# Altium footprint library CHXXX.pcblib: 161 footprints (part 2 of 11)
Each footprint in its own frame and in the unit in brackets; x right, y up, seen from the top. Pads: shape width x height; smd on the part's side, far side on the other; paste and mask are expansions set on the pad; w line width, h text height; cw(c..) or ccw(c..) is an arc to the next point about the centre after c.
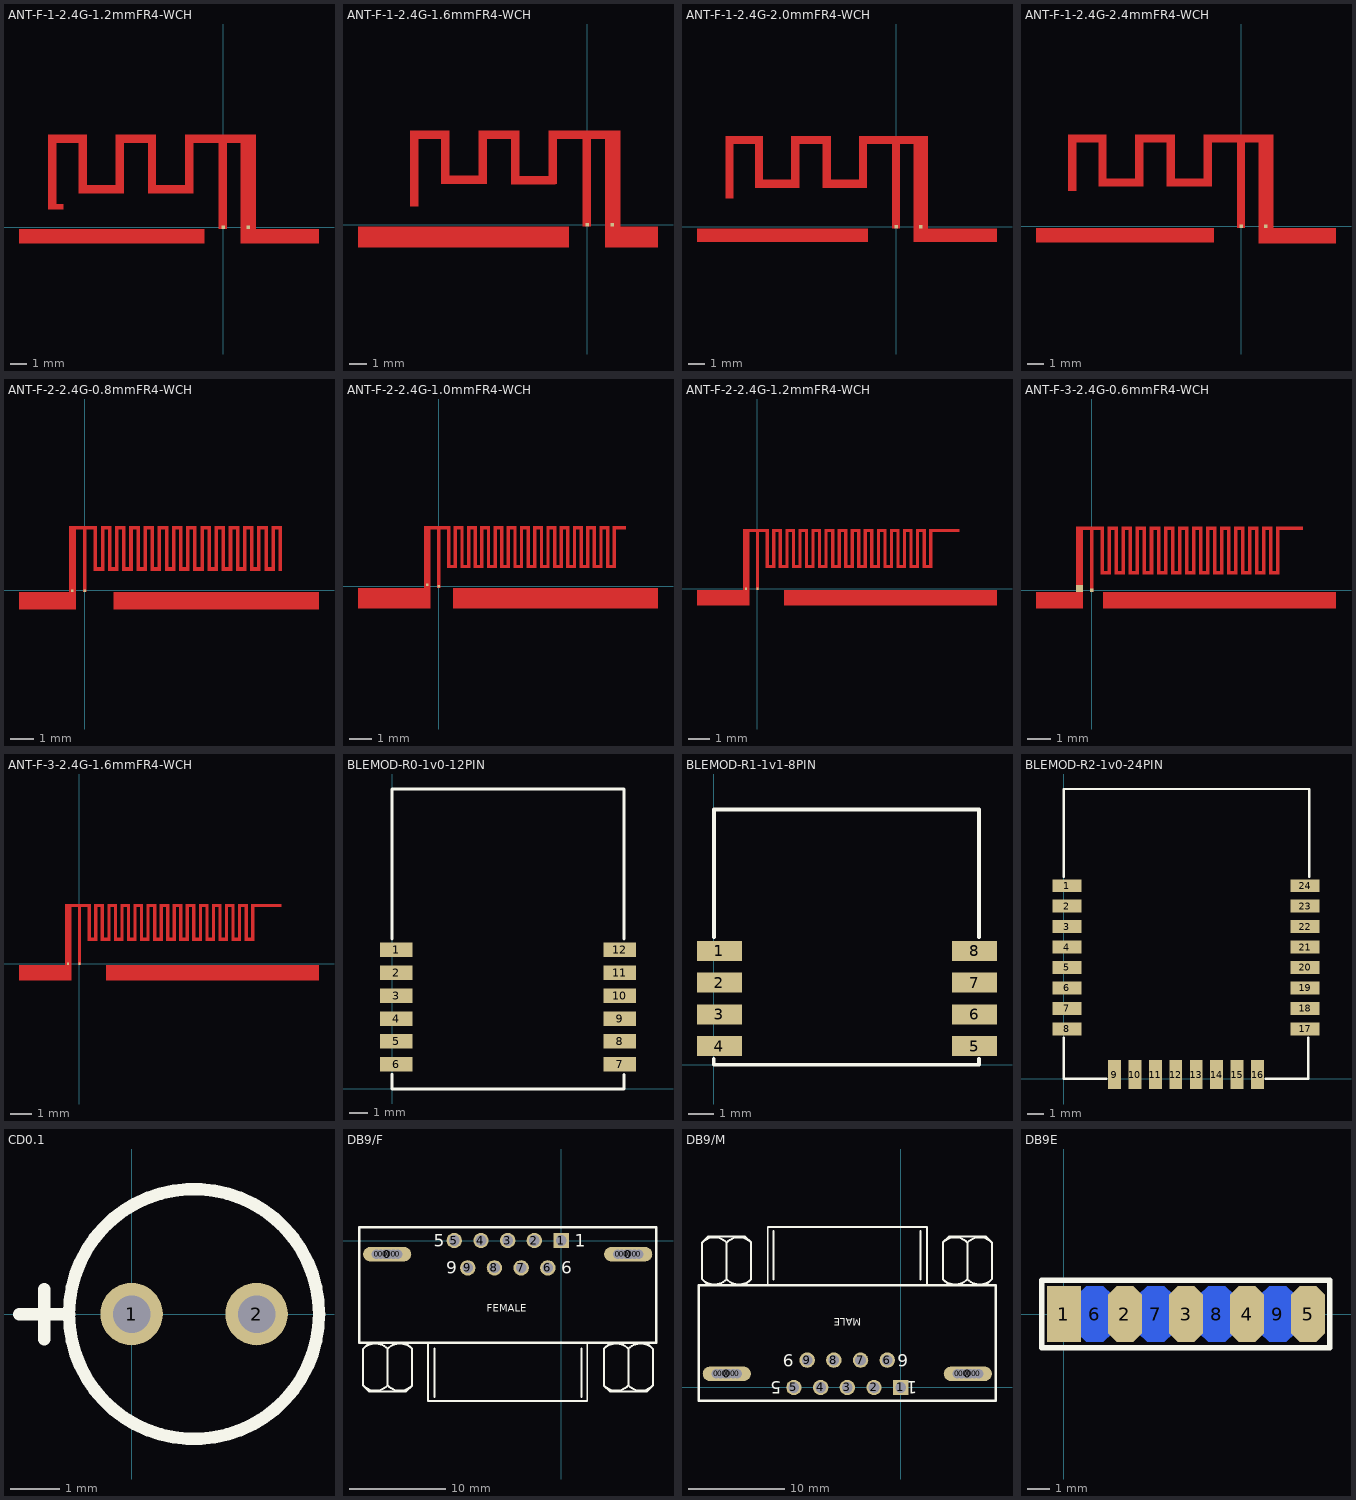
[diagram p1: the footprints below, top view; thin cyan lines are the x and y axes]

## ANT-F-1-2.4G-1.2mmFR4-WCH [mm]
pads (2):
  rect 0.2x0.2 smd mask+0: 0(1.483,0) 1(0,0)
TopLayer:
  region: -9.86,5.18 -10.36,5.18 -10.36,1.06 -9.86,1.06
  region: -8.06,5.5 -10.36,5.5 -10.36,5 -8.06,5
  region: -8.06,5.18 -8.56,5.18 -8.56,2 -8.06,2
  region: -5.875,2.5 -8.364,2.5 -8.364,2 -5.875,2
  region: -5.86,5.18 -6.36,5.18 -6.36,2 -5.86,2
  region: -3.96,5.5 -6.36,5.5 -6.36,5 -3.96,5
  region: -3.96,5.18 -4.46,5.18 -4.46,2 -3.96,2
  region: -1.85,2.5 -4.39,2.5 -4.39,2 -1.85,2
  region: -1.76,5.18 -2.26,5.18 -2.26,2 -1.76,2
  region: 1.94,5.5 -2.26,5.5 -2.26,5 1.94,5
  region: 1.94,5.205 1.04,5.205 1.04,-0.1 1.94,-0.1
  region: 0.24,5.231 -0.26,5.231 -0.26,-0.1 0.24,-0.1
  region: -9.46,1.36 -10.36,1.36 -10.36,1.06 -9.46,1.06
  rectangle: -12.086,-0.978 -1.093,-0.1
  rectangle: 1.04,-0.978 5.679,-0.1
Mechanical13:
  text "适用FR4板材，1.2mm板厚，封装未开窗，建议天线开窗。技术咨询 tech@wch.cn" at -10.498,-4.902 h0.4
  text "GND" at -9.371,-1.808 h0.89
  text "GND" at 0.936,-1.808 h0.89

## ANT-F-1-2.4G-1.6mmFR4-WCH [mm]
pads (2):
  rect 0.2x0.2 smd mask+0: 0(1.483,0) 1(0,0)
TopLayer:
  region: 0.24,5.231 -0.26,5.231 -0.26,-0.1 0.24,-0.1
  region: 1.94,5.206 1.04,5.206 1.04,-0.1 1.94,-0.1
  region: 1.94,5.5 -2.26,5.5 -2.26,5 1.94,5
  region: -1.76,5.181 -2.26,5.181 -2.26,2.361 -1.76,2.361
  region: -1.85,2.855 -4.39,2.855 -4.39,2.36 -1.85,2.36
  region: -3.96,5.18 -4.46,5.18 -4.46,2.36 -3.96,2.36
  region: -3.96,5.5 -6.36,5.5 -6.36,5 -3.96,5
  region: -5.86,5.181 -6.36,5.181 -6.36,2.361 -5.86,2.361
  region: -5.875,2.861 -8.364,2.861 -8.364,2.361 -5.875,2.361
  region: -8.06,5.181 -8.56,5.181 -8.56,2.361 -8.06,2.361
  region: -8.06,5.5 -10.36,5.5 -10.36,5 -8.06,5
  region: -9.86,5.18 -10.36,5.18 -10.36,1.06 -9.86,1.06
  rectangle: 1.04,-1.335 4.149,-0.1
  rectangle: -13.408,-1.335 -1.064,-0.1
Mechanical13:
  text "GND" at -9.082,-1.74 h0.89
  text "GND" at 1.225,-1.74 h0.89
  text "适用FR4板材，1.6mm板厚，封装未开窗，建议天线开窗。技术咨询 tech@wch.cn" at -10.511,-5.125 h0.4

## ANT-F-1-2.4G-2.0mmFR4-WCH [mm]
pads (2):
  rect 0.2x0.2 smd mask+0: 0(1.483,0) 1(0,0)
TopLayer:
  rectangle: 1.04,-0.928 6.113,-0.1
  rectangle: -12.073,-0.928 -1.72,-0.1
  region: 0.24,5.231 -0.26,5.231 -0.26,-0.1 0.24,-0.1
  region: 1.94,5.206 1.04,5.206 1.04,-0.1 1.94,-0.1
  region: 1.94,5.5 -2.26,5.5 -2.26,5 1.94,5
  region: -1.76,5.181 -2.26,5.181 -2.26,2.361 -1.76,2.361
  region: -1.85,2.855 -4.39,2.855 -4.39,2.36 -1.85,2.36
  region: -3.96,5.18 -4.46,5.18 -4.46,2.36 -3.96,2.36
  region: -3.96,5.5 -6.36,5.5 -6.36,5 -3.96,5
  region: -5.86,5.181 -6.36,5.181 -6.36,2.361 -5.86,2.361
  region: -5.875,2.861 -8.364,2.861 -8.364,2.361 -5.875,2.361
  region: -8.06,5.181 -8.56,5.181 -8.56,2.361 -8.06,2.361
  region: -8.06,5.5 -10.36,5.5 -10.36,5 -8.06,5
  region: -9.86,5.18 -10.36,5.18 -10.36,1.7 -9.86,1.7
Mechanical13:
  text "适用FR4板材，2.0mm板厚，封装未开窗，建议天线开窗。技术咨询 tech@wch.cn" at -10.433,-4.732 h0.4
  text "GND" at 1.5,-1.841 h0.89
  text "GND" at -8.807,-1.841 h0.89

## ANT-F-1-2.4G-2.4mmFR4-WCH [mm]
pads (2):
  rect 0.2x0.2 smd mask+0: 0(1.483,0) 1(0,0)
TopLayer:
  rectangle: 1.04,-1.05 5.683,-0.1
  rectangle: -12.291,-0.983 -1.62,-0.1
  region: 0.24,5.231 -0.26,5.231 -0.26,-0.1 0.24,-0.1
  region: 1.94,5.206 1.04,5.206 1.04,-0.1 1.94,-0.1
  region: 1.94,5.5 -2.26,5.5 -2.26,5 1.94,5
  region: -1.76,5.181 -2.26,5.181 -2.26,2.361 -1.76,2.361
  region: -1.85,2.855 -4.39,2.855 -4.39,2.36 -1.85,2.36
  region: -3.96,5.18 -4.46,5.18 -4.46,2.36 -3.96,2.36
  region: -3.96,5.5 -6.36,5.5 -6.36,5 -3.96,5
  region: -5.86,5.181 -6.36,5.181 -6.36,2.361 -5.86,2.361
  region: -5.875,2.861 -8.364,2.861 -8.364,2.361 -5.875,2.361
  region: -8.06,5.181 -8.56,5.181 -8.56,2.361 -8.06,2.361
  region: -8.06,5.5 -10.36,5.5 -10.36,5 -8.06,5
  region: -9.86,5.18 -10.36,5.18 -10.36,2.1 -9.86,2.1
Mechanical13:
  text "适用FR4板材，2.4mm板厚，封装未开窗，建议天线开窗。技术咨询 tech@wch.cn" at -10.269,-5.379 h0.4
  text "GND" at -8.263,-1.666 h0.89
  text "GND" at 2.044,-1.666 h0.89

## ANT-F-2-2.4G-0.8mmFR4-WCH [mm]
pads (2):
  rect 0.1x0.1 smd mask+0: 0(-0.525,-0.025) 1(0,-0.025)
TopLayer:
  rectangle: 7.875,0.825 8.025,2.725
  rectangle: 7.575,0.825 8.025,0.975
  rectangle: 6.675,0.825 6.825,2.725
  rectangle: 6.975,0.825 7.125,2.725
  rectangle: 7.275,0.825 7.425,2.725
  rectangle: 7.575,0.825 7.725,2.725
  rectangle: 6.675,2.575 7.125,2.725
  rectangle: 7.275,2.575 7.725,2.725
  rectangle: 6.375,0.825 6.825,0.975
  rectangle: 6.975,0.825 7.425,0.975
  rectangle: 5.475,0.825 5.625,2.725
  rectangle: 5.775,0.825 5.925,2.725
  rectangle: 6.075,0.825 6.225,2.725
  rectangle: 6.375,0.825 6.525,2.725
  rectangle: 5.475,2.575 5.925,2.725
  rectangle: 6.075,2.575 6.525,2.725
  rectangle: 5.175,0.825 5.625,0.975
  rectangle: 5.775,0.825 6.225,0.975
  rectangle: 4.275,0.825 4.425,2.725
  rectangle: 4.575,0.825 4.725,2.725
  rectangle: 4.875,0.825 5.025,2.725
  rectangle: 5.175,0.825 5.325,2.725
  rectangle: 4.275,2.575 4.725,2.725
  rectangle: 4.875,2.575 5.325,2.725
  rectangle: 3.975,0.825 4.425,0.975
  rectangle: 4.575,0.825 5.025,0.975
  rectangle: 3.075,0.825 3.225,2.725
  rectangle: 3.375,0.825 3.525,2.725
  rectangle: 3.675,0.825 3.825,2.725
  rectangle: 3.975,0.825 4.125,2.725
  rectangle: 3.075,2.575 3.525,2.725
  rectangle: 3.675,2.575 4.125,2.725
  rectangle: 2.775,0.825 3.225,0.975
  rectangle: 3.375,0.825 3.825,0.975
  rectangle: 1.875,0.825 2.025,2.725
  rectangle: 2.175,0.825 2.325,2.725
  rectangle: 2.475,0.825 2.625,2.725
  rectangle: 2.775,0.825 2.925,2.725
  rectangle: 1.875,2.575 2.325,2.725
  rectangle: 2.475,2.575 2.925,2.725
  rectangle: 1.575,0.825 2.025,0.975
  rectangle: 2.175,0.825 2.625,0.975
  rectangle: 0.975,0.825 1.425,0.975
  rectangle: 0.375,0.825 0.825,0.975
  rectangle: 1.275,2.575 1.725,2.725
  rectangle: 0.675,2.575 1.125,2.725
  rectangle: -0.075,2.575 0.525,2.725
  rectangle: 1.575,0.825 1.725,2.725
  rectangle: 1.275,0.825 1.425,2.725
  rectangle: 0.975,0.825 1.125,2.725
  rectangle: 0.675,0.825 0.825,2.725
  rectangle: 0.375,0.825 0.525,2.725
  region: 0.075,2.575 0.075,2.725 -0.675,2.725 -0.675,2.575
  rectangle: -0.075,-0.075 0.075,2.725
  rectangle: -0.675,-0.075 -0.375,2.725
  rectangle: 8.175,0.825 8.325,2.725
  rectangle: 7.875,2.575 8.325,2.725
  rectangle: 1.215,-0.802 9.885,-0.075
  rectangle: -2.777,-0.802 -0.375,-0.075
Mechanical13:
  text "GND" at -2.691,-1.393 h0.89
  text "GND" at 3.964,-1.393 h0.89
  text "适用FR4板材，0.8mm板厚，封装未开窗，建议天线开窗。技术咨询 tech@wch.cn" at -3.002,-4.172 h0.4

## ANT-F-2-2.4G-1.0mmFR4-WCH [mm]
pads (2):
  rect 0.1x0.1 smd mask+0: 0(-0.525,0.075) 1(0,0)
TopLayer:
  rectangle: 0.633,-1.001 9.934,-0.075
  rectangle: -3.664,-1.001 -0.375,-0.075
  rectangle: 7.875,2.575 8.475,2.725
  rectangle: 7.875,0.825 8.025,2.725
  rectangle: 7.575,0.825 8.025,0.975
  rectangle: 6.675,0.825 6.825,2.725
  rectangle: 6.975,0.825 7.125,2.725
  rectangle: 7.275,0.825 7.425,2.725
  rectangle: 7.575,0.825 7.725,2.725
  rectangle: 6.675,2.575 7.125,2.725
  rectangle: 7.275,2.575 7.725,2.725
  rectangle: 6.375,0.825 6.825,0.975
  rectangle: 6.975,0.825 7.425,0.975
  rectangle: 5.475,0.825 5.625,2.725
  rectangle: 5.775,0.825 5.925,2.725
  rectangle: 6.075,0.825 6.225,2.725
  rectangle: 6.375,0.825 6.525,2.725
  rectangle: 5.475,2.575 5.925,2.725
  rectangle: 6.075,2.575 6.525,2.725
  rectangle: 5.175,0.825 5.625,0.975
  rectangle: 5.775,0.825 6.225,0.975
  rectangle: 4.275,0.825 4.425,2.725
  rectangle: 4.575,0.825 4.725,2.725
  rectangle: 4.875,0.825 5.025,2.725
  rectangle: 5.175,0.825 5.325,2.725
  rectangle: 4.275,2.575 4.725,2.725
  rectangle: 4.875,2.575 5.325,2.725
  rectangle: 3.975,0.825 4.425,0.975
  rectangle: 4.575,0.825 5.025,0.975
  rectangle: 3.075,0.825 3.225,2.725
  rectangle: 3.375,0.825 3.525,2.725
  rectangle: 3.675,0.825 3.825,2.725
  rectangle: 3.975,0.825 4.125,2.725
  rectangle: 3.075,2.575 3.525,2.725
  rectangle: 3.675,2.575 4.125,2.725
  rectangle: 2.775,0.825 3.225,0.975
  rectangle: 3.375,0.825 3.825,0.975
  rectangle: 1.875,0.825 2.025,2.725
  rectangle: 2.175,0.825 2.325,2.725
  rectangle: 2.475,0.825 2.625,2.725
  rectangle: 2.775,0.825 2.925,2.725
  rectangle: 1.875,2.575 2.325,2.725
  rectangle: 2.475,2.575 2.925,2.725
  rectangle: 1.575,0.825 2.025,0.975
  rectangle: 2.175,0.825 2.625,0.975
  rectangle: 0.975,0.825 1.425,0.975
  rectangle: 0.375,0.825 0.825,0.975
  rectangle: 1.275,2.575 1.725,2.725
  rectangle: 0.675,2.575 1.125,2.725
  rectangle: 0.075,2.575 0.525,2.725
  rectangle: 1.575,0.825 1.725,2.725
  rectangle: 1.275,0.825 1.425,2.725
  rectangle: 0.975,0.825 1.125,2.725
  rectangle: 0.675,0.825 0.825,2.725
  rectangle: 0.375,0.825 0.525,2.725
  region: 0.075,2.575 0.075,2.725 -0.675,2.725 -0.675,2.575
  rectangle: -0.075,-0.075 0.075,2.725
  rectangle: -0.675,-0.075 -0.375,2.725
Mechanical13:
  text "适用FR4板材，1.0mm板厚，封装未开窗，建议天线开窗。技术咨询 tech@wch.cn" at -3.825,-2.709 h0.4
  text "GND" at -3.874,-1.213 h0.89
  text "GND" at 6.433,-1.213 h0.89

## ANT-F-2-2.4G-1.2mmFR4-WCH [mm]
pads (2):
  rect 0.1x0.1 smd mask+0: 0(-0.525,0) 1(0,0)
TopLayer:
  rectangle: -0.675,-0.05 -0.375,2.75
  rectangle: -0.075,-0.05 0.075,2.75
  region: 0.075,2.6 0.075,2.75 -0.675,2.75 -0.675,2.6
  rectangle: 0.375,0.95 0.525,2.75
  rectangle: 0.675,0.95 0.825,2.75
  rectangle: 0.975,0.95 1.125,2.75
  rectangle: 1.275,0.95 1.425,2.75
  rectangle: 1.575,0.95 1.725,2.75
  rectangle: 0.075,2.6 0.525,2.75
  rectangle: 0.675,2.6 1.125,2.75
  rectangle: 1.275,2.6 1.725,2.75
  rectangle: 0.375,0.95 0.825,1.1
  rectangle: 0.975,0.95 1.425,1.1
  rectangle: 2.175,0.95 2.625,1.1
  rectangle: 1.575,0.95 2.025,1.1
  rectangle: 2.475,2.6 2.925,2.75
  rectangle: 1.875,2.6 2.325,2.75
  rectangle: 2.775,0.95 2.925,2.75
  rectangle: 2.475,0.95 2.625,2.75
  rectangle: 2.175,0.95 2.325,2.75
  rectangle: 1.875,0.95 2.025,2.75
  rectangle: 3.375,0.95 3.825,1.1
  rectangle: 2.775,0.95 3.225,1.1
  rectangle: 3.675,2.6 4.125,2.75
  rectangle: 3.075,2.6 3.525,2.75
  rectangle: 3.975,0.95 4.125,2.75
  rectangle: 3.675,0.95 3.825,2.75
  rectangle: 3.375,0.95 3.525,2.75
  rectangle: 3.075,0.95 3.225,2.75
  rectangle: 4.575,0.95 5.025,1.1
  rectangle: 3.975,0.95 4.425,1.1
  rectangle: 4.875,2.6 5.325,2.75
  rectangle: 4.275,2.6 4.725,2.75
  rectangle: 5.175,0.95 5.325,2.75
  rectangle: 4.875,0.95 5.025,2.75
  rectangle: 4.575,0.95 4.725,2.75
  rectangle: 4.275,0.95 4.425,2.75
  rectangle: 5.775,0.95 6.225,1.1
  rectangle: 5.175,0.95 5.625,1.1
  rectangle: 6.075,2.6 6.525,2.75
  rectangle: 5.475,2.6 5.925,2.75
  rectangle: 6.375,0.95 6.525,2.75
  rectangle: 6.075,0.95 6.225,2.75
  rectangle: 5.775,0.95 5.925,2.75
  rectangle: 5.475,0.95 5.625,2.75
  rectangle: 6.975,0.95 7.425,1.1
  rectangle: 6.375,0.95 6.825,1.1
  rectangle: 7.275,2.6 7.725,2.75
  rectangle: 6.675,2.6 7.125,2.75
  rectangle: 7.575,0.95 7.725,2.75
  rectangle: 7.275,0.95 7.425,2.75
  rectangle: 6.975,0.95 7.125,2.75
  rectangle: 6.675,0.95 6.825,2.75
  rectangle: 7.575,0.95 8.025,1.1
  rectangle: 7.875,2.6 9.275,2.75
  rectangle: 7.875,0.95 8.025,2.75
  rectangle: 1.215,-0.777 10.994,-0.05
  rectangle: -2.777,-0.777 -0.375,-0.05
Mechanical13:
  text "适用FR4板材，1.2mm板厚，封装未开窗，建议天线开窗。技术咨询 tech@wch.cn" at -2.709,-3.856 h0.4
  text "GND" at -3.295,-1.368 h0.89
  text "GND" at 3.964,-1.368 h0.89

## ANT-F-3-2.4G-0.6mmFR4-WCH [mm]
pads (2):
  rect 0.3x0.3 smd mask+0: 0(-0.525,0.075)
  rect 0.15x0.15 smd mask+0: 1(0,0)
TopLayer:
  rectangle: -0.675,-0.075 -0.375,2.725
  rectangle: -0.075,-0.075 0.075,2.725
  region: 0.075,2.575 0.075,2.725 -0.675,2.725 -0.675,2.575
  rectangle: 0.375,0.675 0.525,2.725
  rectangle: 0.675,0.675 0.825,2.725
  rectangle: 0.975,0.675 1.125,2.725
  rectangle: 1.275,0.675 1.425,2.725
  rectangle: 1.575,0.675 1.725,2.725
  rectangle: 0.075,2.575 0.525,2.725
  rectangle: 0.675,2.575 1.125,2.725
  rectangle: 1.275,2.575 1.725,2.725
  rectangle: 0.375,0.675 0.825,0.825
  rectangle: 0.975,0.675 1.425,0.825
  rectangle: 2.175,0.675 2.625,0.825
  rectangle: 1.575,0.675 2.025,0.825
  rectangle: 2.475,2.575 2.925,2.725
  rectangle: 1.875,2.575 2.325,2.725
  rectangle: 2.775,0.675 2.925,2.725
  rectangle: 2.475,0.675 2.625,2.725
  rectangle: 2.175,0.675 2.325,2.725
  rectangle: 1.875,0.675 2.025,2.725
  rectangle: 3.375,0.675 3.825,0.825
  rectangle: 2.775,0.675 3.225,0.825
  rectangle: 3.675,2.575 4.125,2.725
  rectangle: 3.075,2.575 3.525,2.725
  rectangle: 3.975,0.675 4.125,2.725
  rectangle: 3.675,0.675 3.825,2.725
  rectangle: 3.375,0.675 3.525,2.725
  rectangle: 3.075,0.675 3.225,2.725
  rectangle: 4.575,0.675 5.025,0.825
  rectangle: 3.975,0.675 4.425,0.825
  rectangle: 4.875,2.575 5.325,2.725
  rectangle: 4.275,2.575 4.725,2.725
  rectangle: 5.175,0.675 5.325,2.725
  rectangle: 4.875,0.675 5.025,2.725
  rectangle: 4.575,0.675 4.725,2.725
  rectangle: 4.275,0.675 4.425,2.725
  rectangle: 5.775,0.675 6.225,0.825
  rectangle: 5.175,0.675 5.625,0.825
  rectangle: 6.075,2.575 6.525,2.725
  rectangle: 5.475,2.575 5.925,2.725
  rectangle: 6.375,0.675 6.525,2.725
  rectangle: 6.075,0.675 6.225,2.725
  rectangle: 5.775,0.675 5.925,2.725
  rectangle: 5.475,0.675 5.625,2.725
  rectangle: 6.975,0.675 7.425,0.825
  rectangle: 6.375,0.675 6.825,0.825
  rectangle: 7.275,2.575 7.725,2.725
  rectangle: 6.675,2.575 7.125,2.725
  rectangle: 7.575,0.675 7.725,2.725
  rectangle: 7.275,0.675 7.425,2.725
  rectangle: 6.975,0.675 7.125,2.725
  rectangle: 6.675,0.675 6.825,2.725
  rectangle: 7.575,0.675 8.025,0.825
  rectangle: 7.875,2.575 9.025,2.725
  rectangle: 7.875,0.675 8.025,2.725
  rectangle: 0.484,-0.765 10.438,-0.075
  rectangle: -2.388,-0.765 -0.375,-0.075
Mechanical13:
  text "GND" at 4.348,-1.194 h0.89
  text "GND" at -2.911,-1.194 h0.89
  text "适用FR4板材，0.6mm板厚，封装未开窗，建议天线开窗。技术咨询 tech@wch.cn" at -3.041,-2.982 h0.4

## ANT-F-3-2.4G-1.6mmFR4-WCH [mm]
pads (2):
  rect 0.1x0.1 smd mask+0: 0(-0.525,0) 1(0,0)
TopLayer:
  rectangle: 1.215,-0.777 10.994,-0.05
  rectangle: -2.777,-0.777 -0.375,-0.05
  rectangle: -0.675,-0.05 -0.375,2.75
  rectangle: -0.075,-0.05 0.075,2.75
  region: 0.075,2.6 0.075,2.75 -0.675,2.75 -0.675,2.6
  rectangle: 0.375,1.05 0.525,2.75
  rectangle: 0.675,1.05 0.825,2.75
  rectangle: 0.975,1.05 1.125,2.75
  rectangle: 1.275,1.05 1.425,2.75
  rectangle: 1.575,1.05 1.725,2.75
  rectangle: 0.075,2.6 0.525,2.75
  rectangle: 0.675,2.6 1.125,2.75
  rectangle: 1.275,2.6 1.725,2.75
  rectangle: 0.375,1.05 0.825,1.2
  rectangle: 0.975,1.05 1.425,1.2
  rectangle: 2.175,1.05 2.625,1.2
  rectangle: 1.575,1.05 2.025,1.2
  rectangle: 2.475,2.6 2.925,2.75
  rectangle: 1.875,2.6 2.325,2.75
  rectangle: 2.775,1.05 2.925,2.75
  rectangle: 2.475,1.05 2.625,2.75
  rectangle: 2.175,1.05 2.325,2.75
  rectangle: 1.875,1.05 2.025,2.75
  rectangle: 3.375,1.05 3.825,1.2
  rectangle: 2.775,1.05 3.225,1.2
  rectangle: 3.675,2.6 4.125,2.75
  rectangle: 3.075,2.6 3.525,2.75
  rectangle: 3.975,1.05 4.125,2.75
  rectangle: 3.675,1.05 3.825,2.75
  rectangle: 3.375,1.05 3.525,2.75
  rectangle: 3.075,1.05 3.225,2.75
  rectangle: 4.575,1.05 5.025,1.2
  rectangle: 3.975,1.05 4.425,1.2
  rectangle: 4.875,2.6 5.325,2.75
  rectangle: 4.275,2.6 4.725,2.75
  rectangle: 5.175,1.05 5.325,2.75
  rectangle: 4.875,1.05 5.025,2.75
  rectangle: 4.575,1.05 4.725,2.75
  rectangle: 4.275,1.05 4.425,2.75
  rectangle: 5.775,1.05 6.225,1.2
  rectangle: 5.175,1.05 5.625,1.2
  rectangle: 6.075,2.6 6.525,2.75
  rectangle: 5.475,2.6 5.925,2.75
  rectangle: 6.375,1.05 6.525,2.75
  rectangle: 6.075,1.05 6.225,2.75
  rectangle: 5.775,1.05 5.925,2.75
  rectangle: 5.475,1.05 5.625,2.75
  rectangle: 6.975,1.05 7.425,1.2
  rectangle: 6.375,1.05 6.825,1.2
  rectangle: 7.275,2.6 7.725,2.75
  rectangle: 6.675,2.6 7.125,2.75
  rectangle: 7.575,1.05 7.725,2.75
  rectangle: 7.275,1.05 7.425,2.75
  rectangle: 6.975,1.05 7.125,2.75
  rectangle: 6.675,1.05 6.825,2.75
  rectangle: 7.575,1.05 8.025,1.2
  rectangle: 7.875,2.6 9.275,2.75
  rectangle: 7.875,1.05 8.025,2.75
Mechanical13:
  text "GND" at 3.964,-1.368 h0.89
  text "GND" at -2.792,-1.368 h0.89
  text "适用FR4板材，1.6mm板厚，封装未开窗，建议天线开窗。技术咨询 tech@wch.cn" at -2.758,-4.352 h0.4

## BLEMOD-R0-1v0-12PIN [mm]
pads (12):
  rect 1.8x0.8 smd: 1(0.225,7.711) 2(0.225,6.441) 3(0.225,5.171) 4(0.225,3.901) 5(0.225,2.631) 6(0.225,1.361) 7(12.611,1.361) 8(12.611,2.631) 9(12.611,3.901) 10(12.611,5.171) 11(12.611,6.441) 12(12.611,7.711)
TopOverlay:
  lines w0.152: 0,0.822 0,0 12.835,0 12.835,0.796 ; 0,8.303 0,16.606 12.835,16.606 12.835,8.303

## BLEMOD-R1-1v1-8PIN [mm]
pads (8):
  rect 1.8x0.8 smd: 1(0.225,4.553) 2(0.225,3.283) 3(0.225,2.013) 4(0.225,0.743) 5(10.425,0.743) 6(10.425,2.013) 7(10.425,3.283) 8(10.425,4.553)
TopOverlay:
  lines w0.152: -0.008,0.233 -0.008,0 0,0 10.6,0 10.6,0.233 ; 0,5.108 0,10.215 10.6,10.215 10.6,5.108

## BLEMOD-R2-1v0-24PIN [mm]
pads (24):
  rect 1.8x0.8 smd: 1(0.192,12.005) 2(0.192,10.735) 3(0.192,9.465) 4(0.192,8.195) 5(0.192,6.925) 6(0.192,5.655) 7(0.192,4.385) 8(0.192,3.115) 17(14.981,3.115) 18(14.981,4.385) 19(14.981,5.655) 20(14.981,6.925) 21(14.981,8.195) 22(14.981,9.465) 23(14.981,10.735) 24(14.981,12.005)
  rect 0.8x1.8 smd: 9(3.142,0.275) 10(4.412,0.275) 11(5.682,0.275) 12(6.952,0.275) 13(8.222,0.275) 14(9.492,0.275) 15(10.762,0.275) 16(12.032,0.275)
TopOverlay:
  lines w0.152: 0,2.558 0,0 2.643,0 ; 0,12.559 0,18.015 15.256,18.015 15.256,12.564 ; 12.53,0 15.173,0 15.173,2.558

## CD0.1 [mil]
pads (2):
  round 50 hole 30: 1(0,0) 2(100,0)
TopOverlay:
  circle w10: c50,0 r100
  lines w10: -90,0 -50,0 ; -70,-20 -70,20

## DB9/F [mm]
pads (23):
  round 1 hole 1: 0(-19.14,-1.42) 0(-18.7,-1.42) 0(-18.26,-1.42) 0(-17.82,-1.42) 0(-17.38,-1.42) 0(-16.94,-1.42) 0(5.86,-1.42) 0(6.3,-1.42) 0(6.74,-1.42) 0(7.18,-1.42) 0(7.62,-1.42) 0(8.06,-1.42)
  oval 5x1.5 hole 1: 0(-18.04,-1.42) 0(6.96,-1.42)
  rect 1.6x1.6 hole 1.1: 1(0,0)
  round 1.6 hole 1.1: 2(-2.77,0) 3(-5.54,0) 4(-8.31,0) 5(-11.08,0) 6(-1.374,-2.84) 7(-4.143,-2.84) 8(-6.912,-2.84) 9(-9.68,-2.84)
TopOverlay:
  lines w0.203: -20.537,-15.037 ccw(c-19.264,-13.765) -17.992,-15.037 ; -20.537,-11.223 cw(c-19.264,-12.495) -17.992,-11.223 ; -19.899,-10.59 -20.534,-11.225 -20.534,-15.035 -19.899,-15.67 -16.089,-15.67 -15.454,-15.035 -15.454,-11.225 -16.089,-10.59 ; -17.997,-15.037 ccw(c-16.724,-13.765) -15.452,-15.037 ; -17.997,-11.223 cw(c-16.724,-12.495) -15.452,-11.223 ; -17.994,-15.035 -17.994,-11.225 ; -13.795,-10.595 -13.795,-16.62 2.715,-16.62 2.715,-10.595 ; -13.126,-16.254 -13.126,-11.174 ; 2.114,-16.254 2.114,-11.174 ; 4.44,-15.037 ccw(c5.712,-13.765) 6.984,-15.037 ; 4.44,-11.223 cw(c5.712,-12.495) 6.984,-11.223 ; 5.077,-10.59 4.442,-11.225 4.442,-15.035 5.077,-15.67 8.887,-15.67 9.522,-15.035 9.522,-11.225 8.887,-10.59 ; 6.98,-15.037 ccw(c8.252,-13.765) 9.524,-15.037 ; 6.98,-11.223 cw(c8.252,-12.495) 9.524,-11.223 ; 6.982,-15.035 6.982,-11.225
  lines w0.254: -20.94,-10.62 -20.94,1.38 9.86,1.38 9.86,-10.62 -20.94,-10.62
  text "FEMALE" at -7.728,-7.391 h0.76
  text "9" at -11.935,-3.438 h1.27
  text "1" at 1.4,-0.644 h1.27
  text "5" at -13.205,-0.644 h1.27
  text "6" at 0.003,-3.438 h1.27

## DB9/M [mm]
pads (23):
  round 1 hole 1: 0(-19.14,1.42) 0(-18.7,1.42) 0(-18.26,1.42) 0(-17.82,1.42) 0(-17.38,1.42) 0(-16.94,1.42) 0(5.86,1.42) 0(6.3,1.42) 0(6.74,1.42) 0(7.18,1.42) 0(7.62,1.42) 0(8.06,1.42)
  oval 5x1.5 hole 1: 0(-18.04,1.42) 0(6.96,1.42)
  rect 1.6x1.6 hole 1.1: 1(0,0)
  round 1.6 hole 1.1: 2(-2.77,0) 3(-5.54,0) 4(-8.31,0) 5(-11.08,0) 6(-1.4,2.84) 7(-4.168,2.84) 8(-6.937,2.84) 9(-9.706,2.84)
TopOverlay:
  lines w0.203: -20.604,11.223 ccw(c-19.332,12.495) -18.06,11.223 ; -20.604,15.037 cw(c-19.332,13.765) -18.06,15.037 ; -19.967,10.59 -20.602,11.225 -20.602,15.035 -19.967,15.67 -16.157,15.67 -15.522,15.035 -15.522,11.225 -16.157,10.59 ; -18.064,11.223 ccw(c-16.792,12.495) -15.52,11.223 ; -18.064,15.037 cw(c-16.792,13.765) -15.52,15.037 ; -18.062,11.225 -18.062,15.035 ; -13.795,10.595 -13.795,16.62 2.715,16.62 2.715,10.595 ; -13.194,11.174 -13.194,16.254 ; 2.046,11.174 2.046,16.254 ; 4.372,11.223 ccw(c5.644,12.495) 6.917,11.223 ; 4.372,15.037 cw(c5.644,13.765) 6.917,15.037 ; 5.009,10.59 4.374,11.225 4.374,15.035 5.009,15.67 8.819,15.67 9.454,15.035 9.454,11.225 8.819,10.59 ; 6.912,11.223 ccw(c8.184,12.495) 9.457,11.223 ; 6.912,15.037 cw(c8.184,13.765) 9.457,15.037 ; 6.914,11.225 6.914,15.035
  lines w0.254: -20.94,-1.38 -20.94,10.62 9.86,10.62 9.86,-1.38 -20.94,-1.38
  text "9" at -11.103,3.423 h1.27
  text "1" at 1.697,0.623 h1.27
  text "5" at -12.403,0.623 h1.27
  text "6" at 0.797,3.423 h1.27
  text "MALE" at -4.078,7.205 h0.76

## DB9E [mil]
pads (9):
  rect 60x100 smd: 1(0,0)
  oct 60x100 smd: 2(109,0) 3(218,0) 4(327,0) 5(436,0)
  oct 60x100 smd far side: 6(55,0) 7(164,0) 8(273,0) 9(382,0)
TopOverlay:
  lines w10: -40,-60 -40,60 475,60 475,-60 -40,-60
